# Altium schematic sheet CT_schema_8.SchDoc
size 287 x 160 mm
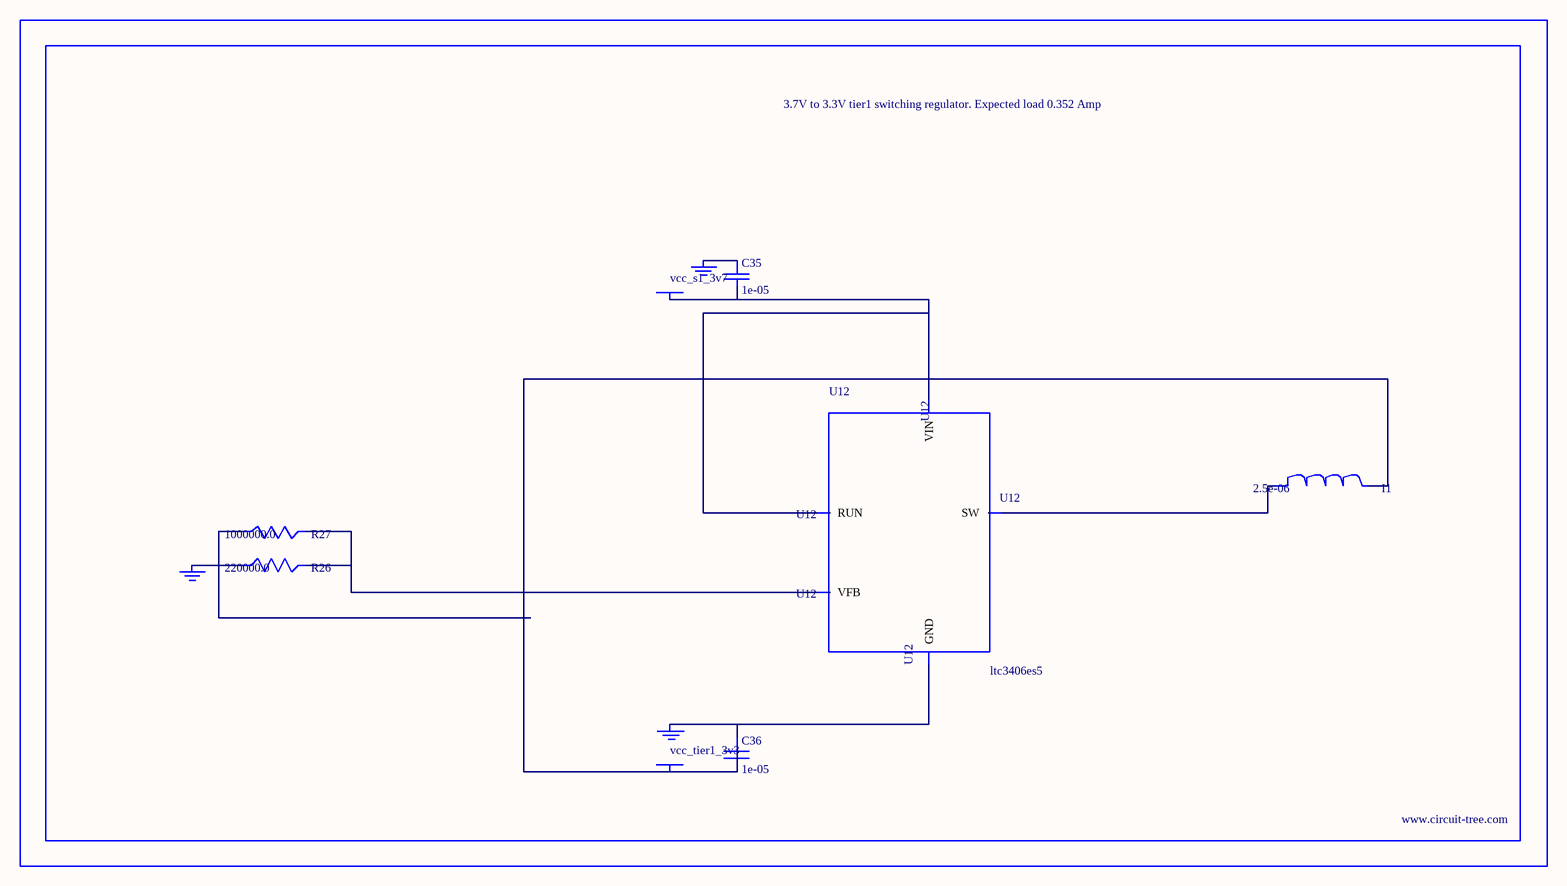
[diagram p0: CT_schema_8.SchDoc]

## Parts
BORDER7  (no value)
C35  1e-05  [C0805]
C36  1e-05  [C0805]
GND_INSTANCE_7_0  (no value)
GND_INSTANCE_7_1  (no value)
GND_INSTANCE_7_2  (no value)
I1  2.5e-06  [DR1040]
POWER_INSTANCE_7_0  vcc_tier1_3v3
POWER_INSTANCE_7_1  vcc_s1_3v7
R26  220000.0  [R0603]
R27  1000000.0  [R0603]
U12  ltc3406es5  [TSOT-23-5]

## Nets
NetC35_1: C35.1 GND_INSTANCE_7_1.0(GND)
NetC35_2: C35.2 POWER_INSTANCE_7_1.0(PWR) U12.1(RUN) U12.4(VIN)
NetC36_1: C36.1 GND_INSTANCE_7_0.0(GND) U12.2(GND)
NetC36_2: C36.2 I1.2 POWER_INSTANCE_7_0.0(PWR) R27.1
NetGND_INSTANCE_7_2_0: GND_INSTANCE_7_2.0(GND) R26.1
NetI1_1: I1.1 U12.3(SW)
NetR26_2: R26.2 R27.2 U12.5(VFB)

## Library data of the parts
BORDER7 = BORDER_PAGE7
C35 C36 = C0805C106K8RACTU
GND_INSTANCE_7_0-GND_INSTANCE_7_2 = GND
I1 = DR1040-2R5-R
POWER_INSTANCE_7_0 POWER_INSTANCE_7_1 = PWR
R26 = RC0603JR-07220KL
R27 = RC0603JR-071ML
